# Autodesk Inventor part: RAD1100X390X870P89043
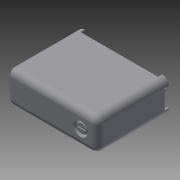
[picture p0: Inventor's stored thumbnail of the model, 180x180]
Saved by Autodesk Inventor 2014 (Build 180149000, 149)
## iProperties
Shininess: 64.0
Length Units: 11272
Angle Units: 11279
Time Units: 11290
Mass Units: 11286
Length Display Precision: 3
Angle Display Precision: 2
Compacted: True
Part Number: RAD1100X390X870P89043
Document SubType Name: Modeling
Created: 2003-04
Designer: t_enrig
Manufacturer: Standard
Standards Organization: Custom
Density: 1 g/cm^3
Mass: 5.63246 g
Surface Area: 20.5625 cm^2
Volume: 5.63246 cm^3
Material: Generic
Appearance: Default
Density: 0.0
Volumn: 0.0
Area: 0.0
PropertySet Name: Model Information
Control State: 0
Master: False
Checked Out: False
Author: t_enrig
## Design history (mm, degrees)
feature "Base1"
body "Solid1"
